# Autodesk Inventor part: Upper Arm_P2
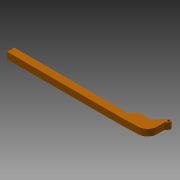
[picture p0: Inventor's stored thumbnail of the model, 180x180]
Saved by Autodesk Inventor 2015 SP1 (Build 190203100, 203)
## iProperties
Created: 2008-11
Part Number: Upper Arm_P2
Document SubType Name: Modeling
Designer: dwoollam
Density: 7.85 g/cm^3
Material: Steel
Appearance: Orange
Mass: 598961 g
Surface Area: 20650.1 cm^2
Volume: 76300.8 cm^3
Dwg_Category: Clearance_Mewp
INSTALLATION: False
CIVIL_WORK: False
EARTHING: False
MOUNTING: False
Author: dwoollam
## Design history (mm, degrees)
sketch "Sketch1"
  geometry: L1 (-215, -170)-(-215, -441.72); L2 (-566.5, -265.2)-(-465, -170); L3 (-465, -170)-(-215, -170); L4 (-15, -78.727)-(32.915, -26.886); L5 (-15, -78.727)-(-15, -241.573); L6 (-207.335, -441.426)-(-566.5, -455.2); L7 (-566.5, -265.2)-(-566.5, -455.2); L8 (-31.21, 28.847)-(-215, -170); L9 (-566.5, -300.2)-(-3030, -300.2); L10 (-3030, -300.2)-(-3030, -455.2); L11 (-3030, -455.2)-(-566.5, -455.2); L12 (-566.5, -455.2)-(-566.5, -300.2); C1 r 25 at (0, 0); A1 r 42.5 centre (0, 0) between (32.915, -26.886) and (-31.21, 28.847); A2 r 200 centre (-215, -241.573) between (-207.335, -441.426) and (-15, -241.573); 1 further point
  constraints: 24 end point, 4 point on circle, 3 centre point, 3 coincident, 3 parallel, 3 tangent, 3 vertical, 2 horizontal, 1 perpendicular, 1 point on line
  dimensions: "d7" = 95.2 vertical distance of L2.end L2.start; "d8" = 101.5 horizontal distance of L2.end L2.start; "d9" = 250 distance of L2.end L1.start; "d12" = 200 distance between parallel lines of L1 L5; "d16" = 215 horizontal distance of L1.start A1.centre; "d17" = 170 vertical distance of L1.start A1.centre; "d18" = 42.5 radius of A1; "d19" = 50 diameter of C1; "d27" = 190 distance of L2.start L6.end; "d29" = 0 distance of L6.end L11.end; "d30" = 155 distance of L11.end L9.start; "d31" = 2463.5 distance of L10.end L11.end; "d43" = 91.27344 vertical distance of L1.start L4.start; "d44" = 13.48035 vertical distance of L11.end L1.end; "d45" = 200 radius of A2
extrude "Main Arm" new body sketch "Sketch1" stored distance "d21" = 140; taper "d22" = 0 deg
body "Solid1"
